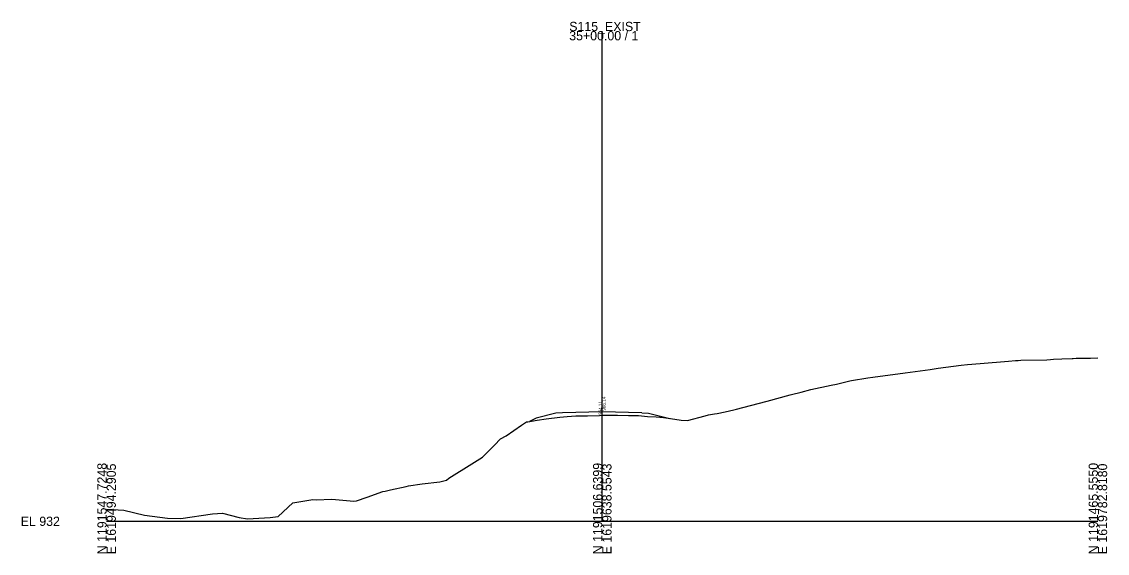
# Model space of a CAD drawing. Extents: x 1620351 to 1620680, y 1192592 to 1195749.
# Drawn here: x 1620351.1 to 1620679.6, y 1193591.8 to 1193752.8 of the extents above; entities that cross this region are included whole.
import ezdxf

# ---------------------------------------------------------------- set-up
doc = ezdxf.new("R2010")
doc.units = 0
for name, color, linetype in [('RD_GPK_XS_Cell', 7, 'Continuous'), ('RD_XS_EarthShd', 7, 'Continuous'), ('RD_XS_ExGround', 7, 'Continuous'), ('RD_XS_Pave', 7, 'Continuous'), ('RD_XS_TieSlope', 7, 'Continuous'), ('RD_XS_TX_Elev_EX', 7, 'Continuous'), ('RD_XS_TX_Elev_PR', 7, 'Continuous')]:
    doc.layers.add(name, color=color, linetype=linetype)

msp = doc.modelspace()

# ---------------------------------------------------------------- linework, layer by layer
at = {"layer": 'RD_GPK_XS_Cell'}
for p, q in [((1620526.76, 1193601.47), (1620526.76, 1193749.94)), ((1620376.76, 1193601.47), (1620526.76, 1193601.47)), ((1620526.76, 1193601.47), (1620676.76, 1193601.47))]:
    msp.add_line(p, q, dxfattribs=at)
at = {"layer": 'RD_XS_EarthShd'}
for p, q in [((1620514.76, 1193634.36), (1620512.76, 1193634.2)), ((1620538.76, 1193634.36), (1620540.76, 1193634.2))]:
    msp.add_line(p, q, dxfattribs=at)
at = {"layer": 'RD_XS_ExGround'}
msp.add_lwpolyline([(1620376.76, 1193605.11), (1620382.01, 1193604.86), (1620388.18, 1193603.29), (1620395.14, 1193602.37), (1620399.22, 1193602.28), (1620408.82, 1193603.75), (1620411.79, 1193603.94), (1620416.89, 1193602.57), (1620419.41, 1193602.24), (1620426.22, 1193602.64), (1620428.68, 1193602.87), (1620433.12, 1193607.04), (1620433.7, 1193607.19), (1620439.13, 1193608.04), (1620440.22, 1193608), (1620444.96, 1193608.22), (1620451.58, 1193607.57), (1620452.36, 1193607.71), (1620455.59, 1193608.74), (1620460.31, 1193610.51), (1620461.02, 1193610.64), (1620462.69, 1193611), (1620467.45, 1193612), (1620468.15, 1193612.16), (1620472.22, 1193612.85), (1620477.65, 1193613.42), (1620479.63, 1193613.93), (1620480.37, 1193614.56), (1620487.25, 1193618.9), (1620490.51, 1193620.86), (1620494.15, 1193624.55), (1620495.95, 1193626.4), (1620497.68, 1193627.33), (1620502.32, 1193630.63), (1620503.81, 1193631.58), (1620504.28, 1193631.63), (1620507.1, 1193632.1), (1620509.83, 1193632.55), (1620513.89, 1193633.05), (1620516.16, 1193633.24), (1620518.72, 1193633.4), (1620522.31, 1193633.46), (1620525.97, 1193633.53), (1620526.76, 1193633.57), (1620527.64, 1193633.62), (1620528.44, 1193633.64), (1620528.96, 1193633.64), (1620529.69, 1193633.64), (1620531.33, 1193633.57), (1620534.73, 1193633.52), (1620537.22, 1193633.49), (1620537.74, 1193633.47), (1620540.45, 1193633.21), (1620543.07, 1193633.08), (1620545.33, 1193632.89), (1620547.38, 1193632.56), (1620550.65, 1193632.13), (1620552.6, 1193631.99), (1620557.89, 1193633.46), (1620558.89, 1193633.67), (1620560.75, 1193633.99), (1620561.54, 1193634.13), (1620564, 1193634.65), (1620566.56, 1193635.21), (1620567.4, 1193635.39), (1620576.29, 1193637.78), (1620576.63, 1193637.87), (1620583.63, 1193639.75), (1620584.08, 1193639.87), (1620586.94, 1193640.62), (1620589.91, 1193641.34), (1620596.08, 1193642.69), (1620597.65, 1193643.05), (1620601.68, 1193643.98), (1620602.22, 1193644.1), (1620607.09, 1193644.89), (1620608.65, 1193645.15), (1620618.39, 1193646.41), (1620626.02, 1193647.48), (1620628.42, 1193647.81), (1620635.34, 1193648.75), (1620637.29, 1193648.92), (1620641.16, 1193649.27), (1620649.69, 1193649.96), (1620651.86, 1193650.12), (1620652.6, 1193650.13), (1620653.46, 1193650.23), (1620661.28, 1193650.37), (1620662.46, 1193650.47), (1620663.32, 1193650.53), (1620665.88, 1193650.64), (1620668.96, 1193650.77), (1620669.29, 1193650.79), (1620670.23, 1193650.83), (1620674.5, 1193650.89), (1620676.76, 1193650.96)], dxfattribs=at)
at = {"layer": 'RD_XS_Pave'}
for p, q in [((1620526.76, 1193634.6), (1620514.76, 1193634.36)), ((1620538.76, 1193634.36), (1620526.76, 1193634.6))]:
    msp.add_line(p, q, dxfattribs=at)
at = {"layer": 'RD_XS_TieSlope'}
for p, q in [((1620506.76, 1193632.7), (1620504.73, 1193631.69)), ((1620512.76, 1193634.2), (1620506.76, 1193632.7)), ((1620540.76, 1193634.2), (1620547.21, 1193632.59))]:
    msp.add_line(p, q, dxfattribs=at)

# ---------------------------------------------------------------- texts
at = {"layer": 'RD_GPK_XS_Cell'}
for s, p in [('S115_EXIST', (1620516.76, 1193749.94)), ('35+00.00 / 1', (1620516.76, 1193747.14)), ('EL 932', (1620350.76, 1193600.07))]:
    msp.add_text(s, height=2.8, dxfattribs=at).set_placement(p)
for s, p in [('N 1191547.7248', (1620376.76, 1193591.47)), ('E 1619494.2905', (1620379.56, 1193591.47)), ('N 1191506.6399', (1620526.76, 1193591.47)), ('E 1619638.5543', (1620529.56, 1193591.47)), ('N 1191465.5550', (1620676.76, 1193591.47)), ('E 1619782.8180', (1620679.56, 1193591.47))]:
    msp.add_text(s, height=2.8, rotation=90, dxfattribs=at).set_placement(p)
at = {"layer": 'RD_XS_TX_Elev_EX'}
msp.add_text('964.11', height=1, rotation=90, dxfattribs=at).set_placement((1620526.66, 1193633.67))
at = {"layer": 'RD_XS_TX_Elev_PR'}
msp.add_text(' 965.14', height=1, rotation=90, dxfattribs=at).set_placement((1620527.76, 1193634.6))

doc.saveas('drawing.dxf')
